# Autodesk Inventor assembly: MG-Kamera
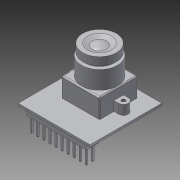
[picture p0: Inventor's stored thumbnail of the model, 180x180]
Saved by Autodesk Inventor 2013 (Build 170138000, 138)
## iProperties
Created: 2012-10
Part Number: MG-Kamera
Document SubType Name: Assembly
Designer: rYan
Mass: 14.7187 g
Surface Area: 47.0108 cm^2
Volume: 5.43124 cm^3
Density: 2.71 g/cm^3
Author: rYan
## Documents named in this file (3)
- D:\SVN\2013\Inventor\Elektronik\MG-Kamera.iam
- D:\SVN\2013\Inventor\Elektronik\Kamera OV7725.ipt
- D:\SVN\2013\Inventor\Elektronik\Objektiv.ipt
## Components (2 placed, 2 different names)
1. Kamera OV7725:1 — Passend:1, Passend:2
2. Objektiv:1 — Passend:1, Passend:2
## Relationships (2: Mate 2)
- Passend:1 [Mate]: Kamera OV7725:1 ↔ Objektiv:1
- Passend:2 [Mate]: Kamera OV7725:1 ↔ Objektiv:1
